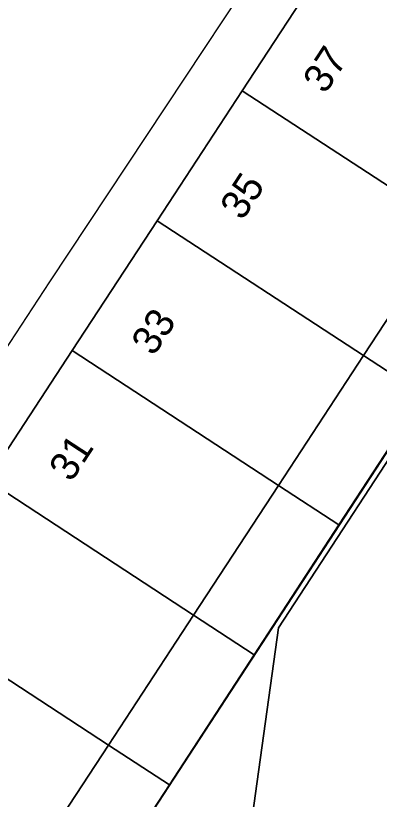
# Model space of a CAD drawing. Extents: x 155640 to 156811, y 382821 to 384049.
# Drawn here: x 156458.45 to 156471.11, y 383720.18 to 383747.46 of the extents above; entities that cross this region are included whole.
import ezdxf

# ---------------------------------------------------------------- set-up
doc = ezdxf.new("R2010")
doc.units = 0
for name, color, linetype in [('IMGEO_Lijnafwatering', 7, 'Continuous'), ('IMGEO_Pand', 7, 'Continuous'), ('IMGEO_Pand_nummerreeks', 7, 'Continuous'), ('IMGEO_Pand_overbouw', 7, 'Continuous'), ('IMGEO_Voetgangersgebied_open', 7, 'Continuous'), ('IMGEO_Voetpad_open', 7, 'Continuous')]:
    doc.layers.add(name, color=color, linetype=linetype)

msp = doc.modelspace()

# ---------------------------------------------------------------- linework, layer by layer
at = {"layer": 'IMGEO_Lijnafwatering'}
for points in [[(156471.067, 383755.451), (156459.635, 383738.197)], [(156459.635, 383738.197), (156449.169, 383722.207)]]:
    msp.add_lwpolyline(points, dxfattribs=at)
at = {"layer": 'IMGEO_Pand'}
msp.add_lwpolyline([(156526.125, 383742.921), (156504.403, 383768.001), (156496.961, 383761.545), (156495.141, 383758.761), (156489.522, 383750.169), (156483.796, 383750.953), (156467.607, 383726.148), (156463.541, 383696.89), (156450.981, 383698.723), (156451.111, 383699.61), (156451.369, 383699.433), (156453.11, 383701.958), (156448.797, 383704.86), (156447.156, 383702.372), (156442.019, 383705.761), (156438.461, 383700.239), (156438.115, 383699.703), (156438.014, 383699.718), (156436.208, 383686.52)], dxfattribs=at)
for points in [[(156476.467, 383744.644), (156469.274, 383749.341), (156466.337, 383744.851), (156473.528, 383740.155)], [(156466.337, 383744.851), (156463.375, 383740.324), (156470.565, 383735.629), (156473.528, 383740.155)], [(156470.565, 383735.629), (156463.375, 383740.324), (156460.417, 383735.804), (156467.606, 383731.11)], [(156460.417, 383735.804), (156457.463, 383731.289), (156464.65, 383726.595), (156467.606, 383731.11)], [(156457.463, 383731.289), (156454.503, 383726.765), (156461.689, 383722.072), (156464.65, 383726.595)], [(156454.503, 383726.765), (156451.542, 383722.239), (156458.727, 383717.547), (156461.689, 383722.072)]]:
    msp.add_lwpolyline(points, close=True, dxfattribs=at)
at = {"layer": 'IMGEO_Pand_overbouw'}
for points in [[(156473.528, 383740.155), (156470.565, 383735.629), (156472.662, 383734.259), (156475.619, 383738.79)], [(156467.606, 383731.11), (156469.71, 383729.736), (156472.662, 383734.259), (156470.565, 383735.629)], [(156467.606, 383731.11), (156464.65, 383726.595), (156466.761, 383725.217), (156469.71, 383729.736)], [(156461.689, 383722.072), (156463.806, 383720.69), (156466.761, 383725.217), (156464.65, 383726.595)], [(156461.689, 383722.072), (156458.727, 383717.547), (156460.85, 383716.161), (156463.806, 383720.69)]]:
    msp.add_lwpolyline(points, close=True, dxfattribs=at)
at = {"layer": 'IMGEO_Voetgangersgebied_open'}
msp.add_lwpolyline([(156430.466, 383687.075), (156432.591, 383702.361), (156438.64, 383701.529), (156438.461, 383700.239), (156442.019, 383705.761), (156443.341, 383707.811), (156442.937, 383708.11), (156445.881, 383712.618), (156445.437, 383712.908), (156448.583, 383717.716), (156451.542, 383722.239), (156454.503, 383726.765), (156457.463, 383731.289), (156460.417, 383735.804), (156463.375, 383740.324), (156466.337, 383744.851), (156469.274, 383749.341)], dxfattribs=at)
at = {"layer": 'IMGEO_Voetpad_open'}
for points in [[(156443.341, 383707.811), (156442.019, 383705.761), (156447.156, 383702.372), (156448.797, 383704.86), (156453.11, 383701.958), (156451.369, 383699.433), (156451.111, 383699.61), (156450.981, 383698.723), (156463.541, 383696.89), (156467.607, 383726.148), (156483.796, 383750.953), (156489.522, 383750.169), (156495.141, 383758.761), (156491.34, 383763.141), (156484.606, 383770.903), (156483.001, 383769.51), (156475.806, 383758.471), (156482.61, 383754.028), (156484.681, 383752.675), (156454.756, 383706.822), (156452.619, 383708.217), (156445.881, 383712.618), (156442.937, 383708.11)], [(156452.619, 383708.217), (156454.756, 383706.822), (156484.681, 383752.675), (156482.61, 383754.028), (156479.445, 383749.193), (156476.467, 383744.644), (156473.528, 383740.155), (156470.565, 383735.629), (156467.606, 383731.11), (156464.65, 383726.595), (156461.689, 383722.072), (156458.727, 383717.547), (156455.766, 383713.025)]]:
    msp.add_lwpolyline(points, close=True, dxfattribs=at)

# ---------------------------------------------------------------- texts
at = {"layer": 'IMGEO_Pand_nummerreeks'}
for s, rotation, p in [('37', 56.8088, (156469.229, 383744.705)), ('35', 56.803, (156466.347, 383740.3)), ('33', 56.7973, (156463.257, 383735.579)), ('31', 56.803, (156460.388, 383731.193))]:
    msp.add_text(s, height=1, rotation=rotation, dxfattribs=at).set_placement(p)

doc.saveas('drawing.dxf')
